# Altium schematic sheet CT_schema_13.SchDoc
size 145 x 119 mm
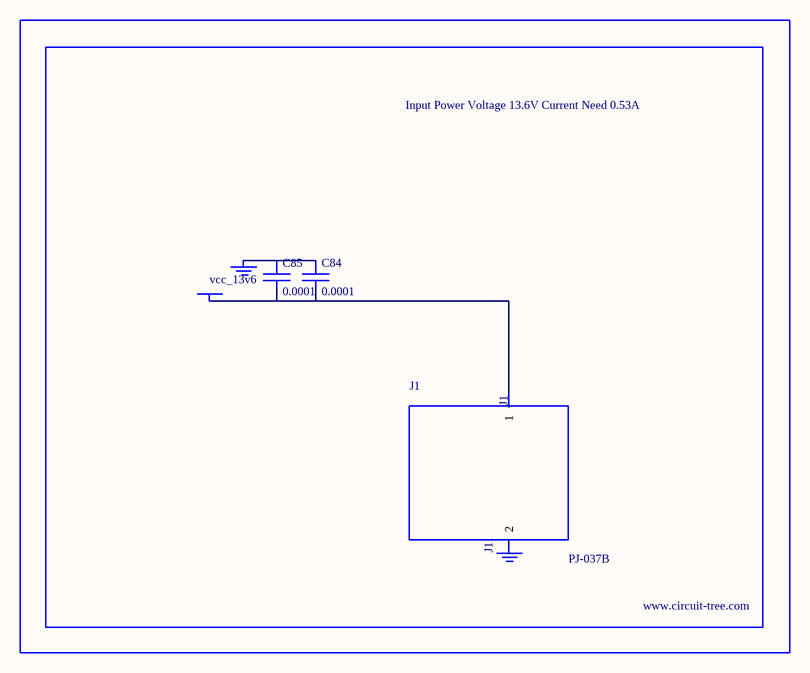
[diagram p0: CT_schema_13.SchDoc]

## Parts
BORDER12  (no value)
C84  0.0001  [EXV-9H]
C85  0.0001  [EXV-9H]
GND_INSTANCE_12_0  (no value)
GND_INSTANCE_12_1  (no value)
J1  PJ-037B  [PJ-037B_PACKAGE]
POWER_INSTANCE_12_0  vcc_13v6

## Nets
NetC84_1: C84.1 C85.1 GND_INSTANCE_12_0.0(GND)
NetC84_2: C84.2 C85.2 J1.1 POWER_INSTANCE_12_0.0(PWR)

Not connected (* = marked no-connect by the designer): GND_INSTANCE_12_1 0(GND); J1 2

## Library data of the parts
BORDER12 = BORDER_PAGE12
C84 C85 = EDK107M035A9HAA
GND_INSTANCE_12_0 GND_INSTANCE_12_1 = GND
POWER_INSTANCE_12_0 = PWR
